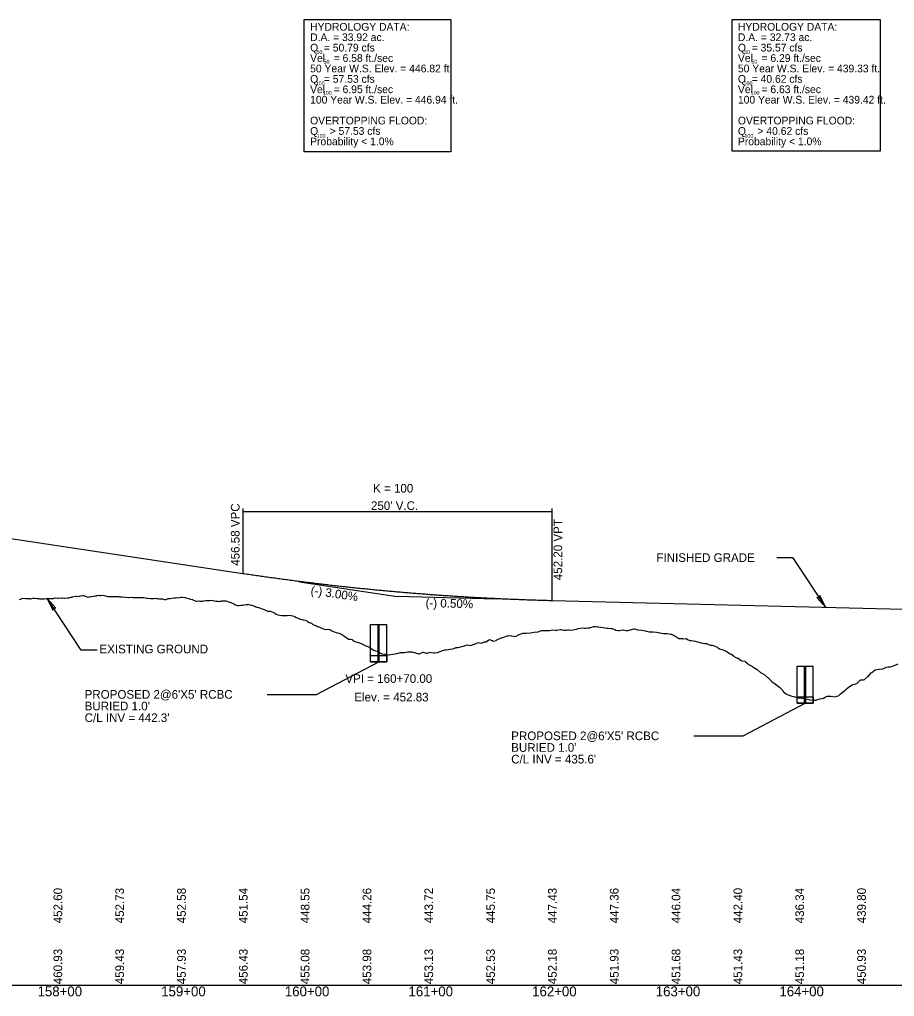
# Model space of a CAD drawing. Extents: x 2017200 to 2047700, y 854850 to 893350.
# Drawn here: x 2025265 to 2025972, y 865091 to 865881 of the extents above; entities that cross this region are included whole.
import ezdxf

# ---------------------------------------------------------------- set-up
doc = ezdxf.new("R2010")
doc.units = 0
for name, color, linetype in [('Culverts', 7, 'Continuous'), ('Default', 7, 'Continuous'), ('RD_DDB_GradeTX', 7, 'Continuous'), ('RD_DDB_Profile_EX', 7, 'Continuous'), ('RD_DDB_Profile_Lbl', 7, 'Continuous'), ('RD_DDB_Profile_PR', 7, 'Continuous'), ('RD_DDB_StaTX', 7, 'Continuous'), ('RD_DDB_StripGrade', 7, 'Continuous'), ('RD_DDB_VCLbl', 7, 'Continuous'), ('RD_GPK_Profile_Cell', 7, 'Continuous'), ('RD_PD_DR_Pipe_TX', 7, 'Continuous'), ('RD_PD_Final_TX', 7, 'Continuous')]:
    doc.layers.add(name, color=color, linetype=linetype)

msp = doc.modelspace()

# ---------------------------------------------------------------- linework, layer by layer
at = {"layer": 'Culverts'}
for p, q in [((2025548.5, 865361.5), (2025548.5, 865391.5)), ((2025548.5, 865391.5), (2025561.5, 865391.5)), ((2025554.5, 865361.5), (2025554.5, 865391.5)), ((2025555.5, 865361.5), (2025555.5, 865391.5)), ((2025561.5, 865361.5), (2025561.5, 865391.5)), ((2025548.5, 865366.5), (2025561.5, 865366.5)), ((2025548.5, 865361.5), (2025561.5, 865361.5)), ((2025893.5, 865328), (2025893.5, 865358)), ((2025893.5, 865358), (2025906.5, 865358)), ((2025899.5, 865328), (2025899.5, 865358)), ((2025900.5, 865328), (2025900.5, 865358)), ((2025906.5, 865328), (2025906.5, 865358)), ((2025893.5, 865333), (2025906.5, 865333)), ((2025893.5, 865328), (2025906.5, 865328))]:
    msp.add_line(p, q, dxfattribs=at)
for points in [[(2025548.5, 865366.5), (2025561.5, 865366.5), (2025561.5, 865361.5), (2025548.5, 865361.5)], [(2025893.5, 865333), (2025906.5, 865333), (2025906.5, 865328), (2025893.5, 865328)]]:
    msp.add_lwpolyline(points, close=True, dxfattribs=at)
at = {"layer": 'Default'}
for points in [[(2025494.84, 865880.55), (2025613.48, 865880.55), (2025613.48, 865773.68), (2025494.84, 865773.68)], [(2025840.84, 865880.55), (2025960.56, 865880.55), (2025960.56, 865774.26), (2025840.84, 865774.26)]]:
    msp.add_lwpolyline(points, close=True, dxfattribs=at)
at = {"layer": 'RD_DDB_GradeTX'}
for p in [(2025490.89, 865426.02), (2025649.97, 865412.15)]:
    msp.add_line(p, (2025570, 865414.15), dxfattribs=at)
at = {"layer": 'RD_DDB_Profile_EX'}
msp.add_lwpolyline([(2025264.41, 865411.73), (2025266.75, 865412.6), (2025267.49, 865412.72), (2025269.62, 865412.67), (2025270.57, 865412.65), (2025272.5, 865412.47), (2025273.06, 865412.42), (2025273.64, 865412.42), (2025275.57, 865412.75), (2025276.72, 865412.79), (2025278.51, 865412.61), (2025279.79, 865412.48), (2025280.61, 865412.4), (2025281.13, 865412.38), (2025283.13, 865412.33), (2025284.01, 865412.36), (2025284.43, 865412.38), (2025285.93, 865412.49), (2025286.88, 865412.56), (2025288.2, 865412.65), (2025288.99, 865412.68), (2025289.76, 865412.63), (2025290.73, 865412.57), (2025292.06, 865412.58), (2025292.63, 865412.78), (2025293.28, 865413), (2025295.12, 865412.9), (2025295.51, 865412.92), (2025295.82, 865412.93), (2025298.39, 865413.16), (2025299.35, 865413.05), (2025300.93, 865412.92), (2025301.26, 865412.91), (2025303.48, 865413.1), (2025304.29, 865413.1), (2025306.05, 865413.54), (2025307.01, 865413.77), (2025307.35, 865413.85), (2025308.61, 865414.21), (2025309.89, 865414.34), (2025310.4, 865414.4), (2025311.18, 865414.23), (2025312.77, 865414.55), (2025313.45, 865414.7), (2025313.76, 865414.79), (2025315.64, 865414.86), (2025316.5, 865414.88), (2025318.52, 865414.13), (2025318.92, 865413.98), (2025319.55, 865413.74), (2025320.45, 865413.93), (2025321.39, 865414.01), (2025322.6, 865414.1), (2025324.27, 865414.43), (2025325.64, 865414.67), (2025326.7, 865414.84), (2025327.15, 865414.92), (2025328.69, 865415.19), (2025329.31, 865414.94), (2025330.02, 865415.05), (2025331.91, 865415.38), (2025333.01, 865415.01), (2025334.77, 865414.39), (2025335.77, 865414.27), (2025337.14, 865414.11), (2025337.81, 865414.14), (2025338.65, 865414.15), (2025339.76, 865414.18), (2025340.85, 865414.15), (2025341.53, 865414.15), (2025342.39, 865414.15), (2025343.88, 865414.09), (2025344.4, 865414.06), (2025345.02, 865414.02), (2025346.92, 865413.87), (2025347.28, 865413.86), (2025347.65, 865413.84), (2025350.3, 865413.63), (2025352.64, 865413.43), (2025353.03, 865413.42), (2025355.59, 865413.52), (2025356.02, 865413.47), (2025358.25, 865413.48), (2025359.05, 865413.38), (2025360.91, 865413.36), (2025361.66, 865413.41), (2025362.08, 865413.43), (2025363.58, 865413.35), (2025364.54, 865413.34), (2025365.1, 865413.33), (2025366.25, 865413.2), (2025367.41, 865412.96), (2025368.13, 865412.81), (2025370.57, 865412.54), (2025371.15, 865412.45), (2025371.61, 865412.53), (2025373.16, 865412.69), (2025374.29, 865412.78), (2025375.23, 865412.66), (2025376.04, 865412.56), (2025377.2, 865412.41), (2025378.92, 865412.25), (2025379.69, 865412.18), (2025380.22, 865412.19), (2025381.79, 865411.8), (2025382.39, 865411.65), (2025383.24, 865411.69), (2025384.67, 865412.45), (2025385.1, 865412.67), (2025386.26, 865412.66), (2025387.81, 865412.78), (2025389.28, 865413.05), (2025390.53, 865413.04), (2025392.3, 865413.24), (2025393.3, 865413.23), (2025395.32, 865413.6), (2025396.17, 865413.53), (2025398.33, 865413.39), (2025398.73, 865413.29), (2025399.05, 865413.19), (2025401.48, 865412.46), (2025401.92, 865412.35), (2025402.79, 865412.14), (2025404.36, 865411.7), (2025404.8, 865411.5), (2025406.98, 865410.53), (2025407.68, 865410.4), (2025409.75, 865410.61), (2025410.55, 865410.34), (2025412.51, 865410.48), (2025413.43, 865410.79), (2025415.29, 865410.85), (2025416.41, 865410.93), (2025418.07, 865410.88), (2025419.42, 865411.2), (2025420.86, 865410.87), (2025422.06, 865410.66), (2025422.43, 865410.6), (2025423.65, 865410.41), (2025424.93, 865410.3), (2025425.44, 865410.25), (2025426.45, 865410.3), (2025427.81, 865410.48), (2025428.45, 865410.57), (2025429.26, 865410.71), (2025430.69, 865410.72), (2025431.46, 865410.72), (2025432.07, 865410.49), (2025433.56, 865409.94), (2025434.47, 865409.6), (2025434.89, 865409.47), (2025436.44, 865408.83), (2025437.72, 865408.24), (2025439.31, 865407.4), (2025440.55, 865406.81), (2025441.77, 865406.93), (2025442.19, 865406.99), (2025443.59, 865407.1), (2025445.07, 865407.3), (2025446.49, 865407.5), (2025447.94, 865407.68), (2025449.09, 865407.82), (2025449.49, 865407.87), (2025450.82, 865407.46), (2025451.95, 865407.11), (2025452.5, 865407.14), (2025453.69, 865406.76), (2025454.82, 865406.39), (2025455.5, 865405.9), (2025456.57, 865405.6), (2025457.7, 865405.29), (2025458.51, 865405.03), (2025459.45, 865404.67), (2025460.58, 865404.24), (2025461.51, 865404.02), (2025462.32, 865403.69), (2025463.47, 865403.23), (2025464.51, 865402.48), (2025465.2, 865402.4), (2025466.37, 865402.27), (2025467.51, 865402.28), (2025468.07, 865402.06), (2025469.28, 865401.58), (2025470.52, 865401.05), (2025470.95, 865400.77), (2025472.19, 865399.98), (2025473.52, 865399.42), (2025473.83, 865399.33), (2025475.11, 865398.99), (2025476.7, 865398.72), (2025478.04, 865398.88), (2025479.58, 865398.8), (2025480.98, 865398.84), (2025482.52, 865399.09), (2025483.92, 865398.81), (2025485.52, 865398.57), (2025486.87, 865398.07), (2025488.21, 865397.33), (2025488.52, 865397.16), (2025489.83, 865396.65), (2025491.08, 865396.13), (2025491.52, 865395.94), (2025492.8, 865395.69), (2025493.96, 865395.41), (2025494.53, 865395.28), (2025495.78, 865394.98), (2025496.83, 865394.4), (2025497.53, 865394.02), (2025498.77, 865393.19), (2025499.71, 865392.84), (2025500.53, 865392.54), (2025501.76, 865391.66), (2025502.59, 865391.24), (2025503.53, 865390.77), (2025504.76, 865390.34), (2025505.46, 865390.06), (2025506.53, 865389.64), (2025507.78, 865389.03), (2025508.34, 865388.76), (2025509.53, 865388.19), (2025510.8, 865387.79), (2025511.22, 865387.71), (2025512.53, 865387.47), (2025514.09, 865387.81), (2025515.53, 865387.5), (2025517.19, 865386.41), (2025518.53, 865385.89), (2025519.91, 865385.26), (2025521.53, 865384.9), (2025522.97, 865384.44), (2025524.53, 865383.78), (2025525.6, 865383.21), (2025526.03, 865382.98), (2025527.53, 865381.92), (2025528.47, 865381.29), (2025529.11, 865380.86), (2025530.54, 865379.82), (2025531.35, 865379.79), (2025532.2, 865379.76), (2025533.54, 865379.33), (2025534.22, 865378.86), (2025535.29, 865378.14), (2025536.54, 865377.65), (2025538.39, 865376.94), (2025539.54, 865376.65), (2025541.49, 865375.9), (2025542.54, 865375.49), (2025544.59, 865374.43), (2025545.54, 865374.07), (2025547.68, 865373.17), (2025548.55, 865372.38), (2025550.78, 865370.69), (2025551.55, 865370.4), (2025553.88, 865370), (2025554.55, 865369.71), (2025556.97, 865368.15), (2025557.55, 865367.93), (2025560.07, 865367.55), (2025560.55, 865367.52), (2025563.17, 865367.1), (2025563.56, 865367.02), (2025566.56, 865367.5), (2025569.56, 865368.04), (2025572.56, 865368.96), (2025575.86, 865368.81), (2025578.65, 865369.35), (2025581.75, 865369.41), (2025584.85, 865368.53), (2025587.57, 865367.87), (2025587.94, 865367.96), (2025590.57, 865369.14), (2025591.04, 865369.07), (2025593.58, 865368.32), (2025594.14, 865368.32), (2025596.58, 865369.24), (2025597.23, 865369.05), (2025599.58, 865368.63), (2025600.33, 865368.61), (2025602.58, 865368.8), (2025604.7, 865369.62), (2025605.58, 865370.08), (2025606.53, 865370.51), (2025608.59, 865371.18), (2025609.62, 865371.14), (2025611.59, 865371.32), (2025612.72, 865371.59), (2025614.59, 865372), (2025615.82, 865372.22), (2025617.59, 865372.98), (2025618.91, 865373), (2025620.59, 865373.27), (2025622.01, 865373.83), (2025623.6, 865373.94), (2025625.11, 865374.58), (2025626.6, 865375.06), (2025628.2, 865374.83), (2025629.6, 865374.54), (2025631.3, 865375.26), (2025632.6, 865375.77), (2025634.4, 865376.45), (2025635.6, 865376.92), (2025637.5, 865376.44), (2025638.61, 865376.6), (2025640.59, 865377.42), (2025641.61, 865377.59), (2025643.69, 865378.99), (2025644.61, 865379.34), (2025646.79, 865378.68), (2025647.61, 865378.1), (2025649.88, 865378.65), (2025650.61, 865379.22), (2025652.98, 865380.18), (2025653.62, 865380.43), (2025656.08, 865381.36), (2025656.62, 865381.51), (2025659.17, 865382.35), (2025659.62, 865382.54), (2025662.27, 865382.52), (2025662.62, 865382.47), (2025665.62, 865381.8), (2025668.63, 865383.44), (2025671.63, 865384.52), (2025673.67, 865384.5), (2025674.66, 865384.5), (2025677.76, 865384.81), (2025680.85, 865385.29), (2025683.63, 865385.69), (2025683.95, 865385.74), (2025686.64, 865386.6), (2025687.05, 865386.65), (2025689.64, 865386.68), (2025690.14, 865386.69), (2025692.64, 865386.79), (2025693.24, 865386.74), (2025695.64, 865387.14), (2025697.9, 865386.84), (2025698.64, 865387.07), (2025699.44, 865387.01), (2025701.65, 865387.56), (2025702.53, 865387.43), (2025704.65, 865387.02), (2025706.64, 865386.93), (2025707.65, 865387.27), (2025708.73, 865387.14), (2025710.65, 865386.97), (2025711.82, 865387.13), (2025713.65, 865387.55), (2025714.92, 865387.77), (2025716.66, 865388.25), (2025718.02, 865388.53), (2025719.66, 865388.9), (2025721.11, 865388.72), (2025722.66, 865388.65), (2025724.11, 865388.75), (2025725.66, 865388.97), (2025727.31, 865389.48), (2025728.66, 865389.98), (2025730.41, 865389.96), (2025731.67, 865389.6), (2025732.85, 865389.6), (2025734.67, 865389.44), (2025736.6, 865389.24), (2025737.67, 865388.79), (2025739.7, 865388.5), (2025740.67, 865388.69), (2025742.79, 865388.25), (2025743.67, 865388.2), (2025745.89, 865387.62), (2025746.68, 865387.07), (2025748.99, 865386.66), (2025749.68, 865386.74), (2025752.08, 865387.17), (2025752.68, 865387.26), (2025755.18, 865386.7), (2025755.68, 865386.56), (2025758.28, 865387.15), (2025758.68, 865387.34), (2025761.38, 865388.07), (2025761.69, 865387.98), (2025764.69, 865387.34), (2025767.69, 865386.94), (2025770.69, 865386.45), (2025771.49, 865386.2), (2025773.69, 865385.5), (2025776.7, 865385.69), (2025779.7, 865385.22), (2025782.37, 865384.87), (2025782.7, 865384.77), (2025785.28, 865384.37), (2025785.7, 865384.29), (2025788.19, 865384.16), (2025788.7, 865384.21), (2025791.1, 865383.69), (2025791.71, 865383.76), (2025794.02, 865382.7), (2025794.71, 865382.21), (2025795.44, 865381.97), (2025797.71, 865380.34), (2025798.54, 865380.17), (2025800.71, 865380.22), (2025801.64, 865380.06), (2025803.71, 865380.1), (2025804.73, 865379.3), (2025806.72, 865378.59), (2025807.83, 865378.63), (2025809.72, 865378.24), (2025810.93, 865377.98), (2025812.72, 865377.55), (2025814.02, 865377.35), (2025815.72, 865376.71), (2025817.12, 865376.34), (2025818.72, 865376.31), (2025820.22, 865376.1), (2025821.73, 865375.31), (2025823.32, 865374.95), (2025824.73, 865374.84), (2025826.41, 865374.4), (2025827.73, 865373.86), (2025829.51, 865372.57), (2025830.73, 865371.96), (2025832.61, 865371.24), (2025833.73, 865371.01), (2025835.7, 865370.02), (2025836.73, 865369.38), (2025838.8, 865368.21), (2025839.74, 865367.8), (2025841.9, 865366.28), (2025842.74, 865365.51), (2025844.99, 865364.46), (2025845.74, 865364.23), (2025848.09, 865362.58), (2025848.74, 865362.22), (2025851.19, 865361.79), (2025851.74, 865361.48), (2025854.29, 865359.29), (2025854.75, 865358.99), (2025857.38, 865357.49), (2025857.75, 865357.16), (2025861.01, 865355.07), (2025863.92, 865352.62), (2025866.83, 865351.08), (2025869.31, 865349.07), (2025869.77, 865348.69), (2025872.87, 865345.46), (2025875.96, 865343.29), (2025879.06, 865340.97), (2025881.76, 865338.09), (2025882.16, 865337.52), (2025884.77, 865335.14), (2025885.26, 865334.92), (2025887.77, 865334.04), (2025888.35, 865333.97), (2025890.77, 865333.38), (2025891.45, 865333.04), (2025893.77, 865332.26), (2025894.55, 865332.33), (2025896.77, 865332.22), (2025897.64, 865332.05), (2025899.78, 865331.77), (2025900.74, 865331.53), (2025902.78, 865331.02), (2025903.84, 865330.77), (2025905.78, 865330.51), (2025906.93, 865330.33), (2025908.78, 865330.29), (2025910.03, 865330.8), (2025911.78, 865331.49), (2025913.43, 865331.64), (2025914.79, 865331.93), (2025916.23, 865332.79), (2025917.79, 865333.52), (2025919.32, 865333.55), (2025920.79, 865333.53), (2025922.42, 865333.26), (2025923.79, 865333.11), (2025925.52, 865333.57), (2025926.79, 865333.89), (2025928.61, 865335.38), (2025929.8, 865336.57), (2025931.71, 865338.06), (2025932.8, 865339.03), (2025934.81, 865340.52), (2025935.8, 865341.4), (2025937.9, 865342.74), (2025938.8, 865343.07), (2025941, 865343.46), (2025941.8, 865343.82), (2025944.1, 865346.2), (2025944.81, 865346.78), (2025947.2, 865346.92), (2025947.81, 865347.2), (2025950.29, 865349.22), (2025950.81, 865349.53), (2025953.39, 865352.51), (2025953.81, 865352.86), (2025956.49, 865354.82), (2025956.81, 865355.04), (2025959.82, 865355.55), (2025962.82, 865355.66), (2025965.82, 865357.11), (2025967.12, 865357.25), (2025968.87, 865357.46), (2025971.97, 865358.42), (2025975.07, 865359.84)], dxfattribs=at)
at = {"layer": 'RD_DDB_Profile_Lbl'}
for p, q in [((2025314.34, 865370.84), (2025286.88, 865412.56)), ((2025327.2, 865370.84), (2025314.34, 865370.84))]:
    msp.add_line(p, q, dxfattribs=at)
msp.add_lwpolyline([(2025876.94, 865445.66), (2025889.8, 865445.66), (2025916.25, 865405.48)], dxfattribs=at)
for points in [[(2025286.88, 865412.56), (2025291.34, 865403.06), (2025291.71, 865405.22), (2025293.84, 865404.7)], [(2025916.25, 865405.48), (2025911.79, 865414.98), (2025911.42, 865412.82), (2025909.29, 865413.33)]]:
    msp.add_lwpolyline(points, close=True, dxfattribs=at)
at = {"layer": 'RD_DDB_Profile_PR'}
for p, q in [((2025200, 865469.65), (2025445, 865432.9)), ((2025695, 865411.02), (2026195, 865398.5))]:
    msp.add_line(p, q, dxfattribs=at)
msp.add_spline([(2025445, 865432.9), (2025450, 865432.16), (2025455, 865431.42), (2025460, 865430.71), (2025465, 865430), (2025470, 865429.31), (2025475, 865428.62), (2025480, 865427.96), (2025485, 865427.3), (2025490, 865426.66), (2025495, 865426.02), (2025500, 865425.41), (2025505, 865424.8), (2025510, 865424.21), (2025515, 865423.62), (2025520, 865423.06), (2025525, 865422.5), (2025530, 865421.96), (2025535, 865421.42), (2025540, 865420.91), (2025545, 865420.4), (2025550, 865419.91), (2025555, 865419.42), (2025560, 865418.96), (2025565, 865418.5), (2025570, 865418.06), (2025575, 865417.62), (2025580, 865417.2), (2025585, 865416.8), (2025590, 865416.4), (2025595, 865416.02), (2025600, 865415.65), (2025605, 865415.3), (2025610, 865414.95), (2025615, 865414.62), (2025620, 865414.3), (2025625, 865414), (2025630, 865413.7), (2025635, 865413.42), (2025640, 865413.15), (2025645, 865412.9), (2025650, 865412.65), (2025655, 865412.42), (2025660, 865412.2), (2025665, 865412), (2025670, 865411.8), (2025675, 865411.62), (2025680, 865411.45), (2025685, 865411.3), (2025690, 865411.15), (2025695, 865411.02)], degree=3, dxfattribs=at)
at = {"layer": 'RD_DDB_VCLbl'}
for p, q in [((2025445, 865485.4), (2025445, 865432.9)), ((2025445, 865482.9), (2025695, 865482.9)), ((2025695, 865485.4), (2025695, 865411.02))]:
    msp.add_line(p, q, dxfattribs=at)
at = {"layer": 'RD_GPK_Profile_Cell'}
msp.add_line((2020500, 865100), (2029700, 865100), dxfattribs=at)
at = {"layer": 'RD_PD_DR_Pipe_TX'}
for p, q in [((2025504.77, 865335.06), (2025555, 865361.5)), ((2025464.77, 865335.06), (2025504.77, 865335.06)), ((2025849.77, 865301.56), (2025900, 865328)), ((2025809.77, 865301.56), (2025849.77, 865301.56))]:
    msp.add_line(p, q, dxfattribs=at)

# ---------------------------------------------------------------- texts
at = {"layer": 'RD_DDB_GradeTX'}
for s, rotation, p in [('(-) 3.00%', 351.46923, (2025499.65, 865415.99)), ('(-) 0.50%', 358.56593, (2025592.82, 865405.64))]:
    msp.add_text(s, height=7, rotation=rotation, dxfattribs=at).set_placement(p)
at = {"layer": 'RD_DDB_Profile_Lbl'}
for s, p in [('FINISHED GRADE', (2025779.62, 865442.11)), ('EXISTING GROUND', (2025329.14, 865368.23)), ('VPI = 160+70.00', (2025528.04, 865344.36)), ('Elev. = 452.83', (2025535.27, 865329.36))]:
    msp.add_text(s, height=7, dxfattribs=at).set_placement(p)
at = {"layer": 'RD_DDB_StaTX'}
for s, p in [('158+00', (2025279.1, 865091)), ('158+00', (2025279.1, 865091)), ('159+00', (2025379.1, 865091)), ('159+00', (2025379.1, 865091)), ('160+00', (2025479.1, 865091)), ('160+00', (2025479.1, 865091)), ('161+00', (2025579.1, 865091)), ('161+00', (2025579.1, 865091)), ('162+00', (2025679.1, 865091)), ('162+00', (2025679.1, 865091)), ('163+00', (2025779.1, 865091)), ('163+00', (2025779.1, 865091)), ('164+00', (2025879.1, 865091)), ('164+00', (2025879.1, 865091))]:
    msp.add_text(s, height=8, dxfattribs=at).set_placement(p)
at = {"layer": 'RD_DDB_StripGrade'}
for s, p in [('456.58 VPC', (2025442.46, 865438.99)), ('452.20 VPT', (2025703.42, 865427.35)), ('452.60', (2025299, 865150)), ('452.73', (2025349, 865150)), ('452.58', (2025399, 865150)), ('451.54', (2025449, 865150)), ('448.55', (2025499, 865150)), ('444.26', (2025549, 865150)), ('443.72', (2025599, 865150)), ('445.75', (2025649, 865150)), ('447.43', (2025699, 865150)), ('447.36', (2025749, 865150)), ('446.04', (2025799, 865150)), ('442.40', (2025849, 865150)), ('436.34', (2025899, 865150)), ('439.80', (2025949, 865150)), ('460.93', (2025299, 865100.75)), ('459.43', (2025349, 865100.75)), ('457.93', (2025399, 865100.75)), ('456.43', (2025449, 865100.75)), ('455.08', (2025499, 865100.75)), ('453.98', (2025549, 865100.75)), ('453.13', (2025599, 865100.75)), ('452.53', (2025649, 865100.75)), ('452.18', (2025699, 865100.75)), ('451.93', (2025749, 865100.75)), ('451.68', (2025799, 865100.75)), ('451.43', (2025849, 865100.75)), ('451.18', (2025899, 865100.75)), ('450.93', (2025949, 865100.75))]:
    msp.add_text(s, height=7, rotation=90, dxfattribs=at).set_placement(p)
at = {"layer": 'RD_DDB_VCLbl'}
for s, p in [('K = 100', (2025550.44, 865498.15)), ("250' V.C.", (2025548.75, 865484.15))]:
    msp.add_text(s, height=7, dxfattribs=at).set_placement(p)
at = {"layer": 'RD_PD_DR_Pipe_TX'}
for s, p in [("PROPOSED 2@6'X5' RCBC", (2025317.17, 865331.56)), ("BURIED 1.0'", (2025317.17, 865322.13)), ("C/L INV = 442.3'", (2025317.17, 865312.7)), ("PROPOSED 2@6'X5' RCBC", (2025662.17, 865298.06)), ("BURIED 1.0'", (2025662.17, 865288.63)), ("C/L INV = 435.6'", (2025662.17, 865279.2))]:
    msp.add_text(s, height=7, dxfattribs=at).set_placement(p)
at = {"layer": 'RD_PD_Final_TX'}
for s, height, p in [('HYDROLOGY DATA:', 6.25, (2025499.55, 865871.54)), ('HYDROLOGY DATA:', 6.25, (2025845.55, 865871.54)), ('D.A. = 33.92 ac.', 6.25, (2025499.55, 865863.13)), ('D.A. = 32.73 ac.', 6.25, (2025845.55, 865863.13)), ('Q  = 50.79 cfs', 6.25, (2025499.55, 865854.71)), ('Q  = 35.57 cfs', 6.25, (2025845.55, 865854.71)), ('Vel   = 6.58 ft./sec', 6.25, (2025499.55, 865846.29)), ('50', 3.125, (2025504.69, 865852.75)), ('Vel   = 6.29 ft./sec', 6.25, (2025845.55, 865846.29)), ('50', 3.125, (2025850.69, 865852.75)), ('50 Year W.S. Elev. = 446.82 ft.', 6.25, (2025499.55, 865837.87)), ('50', 3.125, (2025510.43, 865844.98)), ('50 Year W.S. Elev. = 439.33 ft.', 6.25, (2025845.55, 865837.87)), ('50', 3.125, (2025856.43, 865844.98)), ('Q  = 57.53 cfs', 6.25, (2025499.55, 865829.45)), ('Q  = 40.62 cfs', 6.25, (2025845.55, 865829.45)), ('100', 3.125, (2025504.09, 865827.41)), ('100', 3.125, (2025850.09, 865827.41)), ('Vel   = 6.95 ft./sec', 6.25, (2025499.55, 865821.03)), ('100', 3.125, (2025509.81, 865819.75)), ('Vel   = 6.63 ft./sec', 6.25, (2025845.55, 865821.03)), ('100', 3.125, (2025855.81, 865819.75)), ('100 Year W.S. Elev. = 446.94 ft.', 6.25, (2025499.55, 865812.62)), ('100 Year W.S. Elev. = 439.42 ft.', 6.25, (2025845.55, 865812.62)), ('OVERTOPPING FLOOD:', 6.25, (2025499.55, 865795.78)), ('OVERTOPPING FLOOD:', 6.25, (2025845.55, 865795.78)), ('Q    > 57.53 cfs', 6.25, (2025499.55, 865787.36)), ('Q    > 40.62 cfs', 6.25, (2025845.55, 865787.36)), ('Probability < 1.0%', 6.25, (2025499.55, 865778.94)), ('100', 3.125, (2025504.84, 865784.99)), ('Probability < 1.0%', 6.25, (2025845.55, 865778.94)), ('100', 3.125, (2025850.84, 865784.99))]:
    msp.add_text(s, height=height, rotation=360, dxfattribs=at).set_placement(p)

doc.saveas('drawing.dxf')
